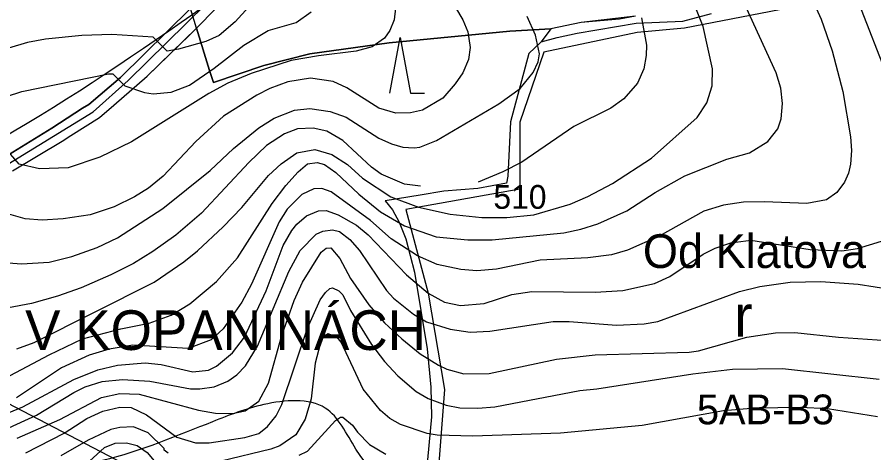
# Model space of a CAD drawing. Extents: x -684583 to -680383, y -1157874 to -1154904.
# Drawn here: x -683807 to -683375.1, y -1157544.1 to -1157324.4 of the extents above; entities that cross this region are included whole.
import ezdxf

# ---------------------------------------------------------------- set-up
doc = ezdxf.new("R2010")
doc.units = 0
for name, color, linetype in [('01_DOPRAVA', 7, 'Continuous'), ('01_MÍSTNÍ_NÁZVY', 7, 'Continuous'), ('01_VRSTEVNICE', 7, 'Continuous'), ('02_KULTURY STAV', 7, 'Continuous'), ('04_ZPF_OP_ORGAN', 7, 'Continuous'), ('06_BIOGEOGRAFIE', 7, 'Continuous'), ('06_ÚSES_BC', 7, 'Continuous')]:
    doc.layers.add(name, color=color, linetype=linetype)

msp = doc.modelspace()

# ---------------------------------------------------------------- linework, layer by layer
at = {"layer": '01_DOPRAVA'}
msp.add_lwpolyline([(-683848.9, -1157421.35), (-683768.73, -1157372.16), (-683751.13, -1157356.37), (-683692.43, -1157298.55), (-683668.13, -1157274.02), (-683656.09, -1157268.45), (-683636.34, -1157266.75), (-683560.15, -1157260.5), (-683520.41, -1157256.3), (-683504.28, -1157253.8), (-683468.06, -1157246.75), (-683377.9, -1157224.15), (-683360.31, -1157216.54), (-683346.34, -1157208.36), (-683325.33, -1157193.59), (-683264.93, -1157143.95), (-683216.9, -1157105.1), (-683205.43, -1157097.83), (-683190.89, -1157090.67), (-683176.02, -1157086.02), (-683159.33, -1157083.06), (-683139, -1157080.79)], dxfattribs=at)
at = {"layer": '01_VRSTEVNICE'}
for points in [[(-683699.38, -1157246.32), (-683697.52, -1157251.89), (-683693.81, -1157258.73), (-683684.83, -1157281.13), (-683677.27, -1157289.83), (-683677.98, -1157301.81), (-683679.83, -1157307.66), (-683697.09, -1157326.77), (-683705.22, -1157333.62), (-683711.93, -1157336.76), (-683725.62, -1157340.61), (-683731.33, -1157341.61), (-683738.46, -1157334.48), (-683759.29, -1157333.19), (-683774.41, -1157333.76), (-683792.67, -1157335.47), (-683801.8, -1157337.19), (-683821.2, -1157342.89)], [(-683613.79, -1157275.14), (-683617.07, -1157295.82), (-683615.65, -1157313.79), (-683616.93, -1157325.78), (-683619.07, -1157331.2), (-683621.78, -1157335.05), (-683628.05, -1157339.33), (-683636.04, -1157341.61), (-683655.16, -1157343.89), (-683668.85, -1157346.32), (-683689.11, -1157352.88), (-683700.8, -1157357.73), (-683710.36, -1157362.86), (-683749.3, -1157387.25), (-683765.42, -1157395.1), (-683781.25, -1157400.38), (-683795.8, -1157400.95), (-683806.08, -1157398.52), (-683813.63, -1157389.82)], [(-683408.95, -1157309.3), (-683401.68, -1157325.49), (-683396.12, -1157341.47), (-683390.7, -1157362.01), (-683386.84, -1157384.83), (-683386.42, -1157391.68), (-683386.84, -1157398.52), (-683387.84, -1157403.09), (-683389.84, -1157407.65), (-683393.69, -1157412.79), (-683398.97, -1157416.5), (-683408.95, -1157418.49), (-683430.21, -1157417.49), (-683440.91, -1157417.78), (-683450.89, -1157419.21), (-683460.88, -1157422.34), (-683483.41, -1157434.9), (-683499.39, -1157441.89), (-683507.38, -1157444.31), (-683519.36, -1157445.74), (-683543.33, -1157447.02), (-683565.29, -1157451.59), (-683575.28, -1157452.44), (-683583.26, -1157451.73), (-683595.25, -1157449.16), (-683605.23, -1157444.88), (-683618.5, -1157436.18), (-683628.91, -1157426.91), (-683648.74, -1157412.5), (-683653.45, -1157410.79), (-683657.44, -1157410.93), (-683663.43, -1157413.93), (-683670.85, -1157421.2), (-683674.98, -1157427.62), (-683688.82, -1157459), (-683693.81, -1157468.13), (-683703.09, -1157481.68), (-683709.22, -1157487.1), (-683720.77, -1157491.53), (-683748.73, -1157489.81), (-683760.71, -1157491.81), (-683770.7, -1157494.81), (-683784.68, -1157501.23), (-683807.36, -1157516.35)], [(-683589.26, -1157314.08), (-683582.27, -1157325.78), (-683579.84, -1157331.77), (-683578.56, -1157339.75), (-683579.41, -1157345.74), (-683582.41, -1157352.59), (-683586.12, -1157358.15), (-683592.39, -1157365.29), (-683602.67, -1157371.28), (-683608.66, -1157372.71), (-683616.07, -1157372.85), (-683624.63, -1157370.42), (-683640.89, -1157360.15), (-683647.74, -1157356.87), (-683659.15, -1157355.16), (-683670.56, -1157357.01), (-683679.69, -1157360.44), (-683686.25, -1157363.72), (-683702.94, -1157374.42), (-683716.92, -1157387.11), (-683733.47, -1157404.66), (-683740.74, -1157410.65), (-683747.88, -1157415.07), (-683758.15, -1157420.06), (-683770.13, -1157424.06), (-683783.82, -1157426.2), (-683794.38, -1157426.77), (-683802.94, -1157426.2), (-683824.33, -1157420.06)], [(-683567.57, -1157436.75), (-683531.34, -1157433.19), (-683522.78, -1157431.33), (-683514.23, -1157428.62), (-683499.68, -1157422.06), (-683485.41, -1157412.93), (-683470.43, -1157404.51), (-683449.18, -1157396.1), (-683437.77, -1157392.82), (-683428.64, -1157387.11), (-683423.5, -1157380.84), (-683421.79, -1157375.7), (-683421.22, -1157368), (-683422.08, -1157360.29), (-683424.36, -1157352.59), (-683441.19, -1157315.93)], [(-683807.22, -1157491.67), (-683798.51, -1157488.53), (-683737.89, -1157458.01), (-683722.91, -1157447.88), (-683716.07, -1157442.31), (-683703.09, -1157430.19), (-683693.81, -1157420.35), (-683680.26, -1157404.37), (-683673.84, -1157398.38), (-683666, -1157392.82), (-683656.87, -1157391.25), (-683648.31, -1157393.67), (-683640.46, -1157398.81), (-683632.91, -1157405.66), (-683618.64, -1157415.07), (-683604.66, -1157420.21), (-683588.69, -1157423.77), (-683572.71, -1157425.48), (-683560.16, -1157425.48), (-683546.46, -1157424.06), (-683528.2, -1157418.78), (-683519.36, -1157414.93), (-683506.81, -1157408.37), (-683487.27, -1157395.53), (-683464.16, -1157374.99), (-683459.31, -1157367.71), (-683456.6, -1157359.15), (-683456.45, -1157350.59), (-683461.16, -1157329.2), (-683465.16, -1157319.07)], [(-683368.16, -1157354.3), (-683382.57, -1157317.79)], [(-683843.45, -1157374.56), (-683804.65, -1157362.01), (-683761, -1157353.02), (-683758.86, -1157353.02), (-683752.73, -1157359.01), (-683742.74, -1157362.43), (-683738.46, -1157363.15), (-683729.33, -1157362.29), (-683720.06, -1157358.73), (-683707.65, -1157350.17), (-683692.82, -1157338.61), (-683680.41, -1157331.2), (-683666.28, -1157327.2), (-683658.72, -1157321.78)], [(-683818.34, -1157447.74), (-683804.79, -1157448.88), (-683790.95, -1157448.02), (-683779.54, -1157445.17), (-683766.7, -1157440.6), (-683756.43, -1157435.75), (-683733.61, -1157420.92), (-683709.79, -1157401.8), (-683697.95, -1157390.68), (-683685.11, -1157380.26), (-683677.41, -1157375.41), (-683667.14, -1157371.42), (-683659.44, -1157370.56), (-683649.17, -1157371.99), (-683641.18, -1157374.84), (-683624.63, -1157385.4), (-683618.36, -1157388.4), (-683612.65, -1157389.96), (-683606.94, -1157390.39), (-683604.09, -1157389.96), (-683595.53, -1157386.68), (-683564.15, -1157368.14), (-683553.45, -1157360.44), (-683546.89, -1157352.31), (-683544.32, -1157347.03), (-683543.75, -1157342.89), (-683545.61, -1157333.48), (-683549.89, -1157324.06)], [(-683492.26, -1157324.78), (-683489.69, -1157338.61), (-683489.83, -1157343.75), (-683491.12, -1157350.59), (-683494.25, -1157357.73), (-683501.24, -1157365.71), (-683507.66, -1157370.42), (-683526.35, -1157379.55), (-683552.6, -1157397.53), (-683562.15, -1157402.52), (-683574.56, -1157407.65)], [(-683603.66, -1157409.65), (-683611.79, -1157408.65), (-683623.49, -1157403.66), (-683628.34, -1157400.09), (-683642.89, -1157386.68), (-683650.88, -1157381.98), (-683657.72, -1157380.41), (-683665.71, -1157380.84), (-683672.28, -1157383.26), (-683681.26, -1157389.11), (-683690.25, -1157397.67), (-683714.07, -1157423.34), (-683727.05, -1157434.33), (-683738.6, -1157442.6), (-683748.3, -1157448.59), (-683759.86, -1157454.44), (-683774.69, -1157460.86), (-683786.68, -1157465.14), (-683799.8, -1157468.85), (-683825.76, -1157473.7)], [(-683816.06, -1157507.93), (-683790.95, -1157494.66), (-683774.12, -1157486.68), (-683754.72, -1157481.54), (-683740.46, -1157478.83), (-683729.33, -1157474.7), (-683719.92, -1157468.99), (-683706.51, -1157457.72), (-683695.95, -1157445.88), (-683678.41, -1157418.49), (-683671.56, -1157409.36), (-683665.29, -1157402.38), (-683660.72, -1157398.38), (-683655.73, -1157397.67), (-683652.02, -1157398.81), (-683646.31, -1157402.8), (-683634.76, -1157413.64), (-683623.92, -1157422.63), (-683611.79, -1157429.62), (-683595.82, -1157435.18), (-683579.84, -1157436.75), (-683567.57, -1157436.75)], [(-683818.06, -1157526.62), (-683804.08, -1157520.91), (-683778.4, -1157507.07), (-683766.42, -1157502.23), (-683756.43, -1157499.94), (-683742.46, -1157498.8), (-683734.47, -1157499.52), (-683718.49, -1157503.22), (-683710.5, -1157502.37), (-683706.51, -1157500.37), (-683698.38, -1157493.67), (-683692.39, -1157485.82), (-683681.4, -1157462.43), (-683672.85, -1157439.6), (-683668.57, -1157432.04), (-683666, -1157428.91), (-683661.15, -1157424.63), (-683655.16, -1157422.06), (-683651.16, -1157421.92), (-683645.17, -1157424.06), (-683635.9, -1157429.33), (-683630.05, -1157434.18), (-683610.79, -1157454.44), (-683599.81, -1157463.57), (-683591.54, -1157468.13), (-683583.55, -1157469.85), (-683571.57, -1157468.85), (-683557.59, -1157464.28), (-683547.6, -1157462.86), (-683515.65, -1157463.14), (-683501.67, -1157462.28), (-683485.7, -1157458.72), (-683477.99, -1157455.3), (-683461.16, -1157443.88), (-683455.17, -1157440.89), (-683447.18, -1157438.18), (-683437.2, -1157436.89), (-683407.24, -1157441.6), (-683391.27, -1157442.31), (-683383.28, -1157441.17), (-683371.3, -1157437.32)], [(-683817.2, -1157534.18), (-683797.23, -1157525.19), (-683778.4, -1157513.78), (-683772.7, -1157510.93), (-683764.14, -1157508.22), (-683753.87, -1157507.08), (-683740.17, -1157508.07), (-683719.63, -1157511.92), (-683714.92, -1157511.92), (-683707.65, -1157510.78), (-683700.8, -1157508.07), (-683696.24, -1157504.79), (-683691.96, -1157500.23), (-683685.83, -1157490.39), (-683670.13, -1157452.73), (-683664.29, -1157442.17), (-683656.3, -1157433.9), (-683652.88, -1157432.33), (-683648.03, -1157431.62), (-683644.46, -1157432.61), (-683639.32, -1157436.61), (-683634.47, -1157442.17), (-683620.78, -1157462.28), (-683617.21, -1157466.14), (-683607.23, -1157474.27), (-683600.67, -1157478.12), (-683588.69, -1157481.83), (-683578.7, -1157483.25), (-683568.72, -1157482.83), (-683536.76, -1157477.98), (-683528.78, -1157477.83), (-683504.81, -1157479.69), (-683490.83, -1157479.12), (-683483.98, -1157477.83), (-683442.9, -1157462.71), (-683432.63, -1157460.29), (-683417.23, -1157458.15), (-683401.82, -1157457.72), (-683382.99, -1157459.15), (-683365.88, -1157461.71)], [(-683807.07, -1157536.74), (-683785.53, -1157527.33), (-683764.42, -1157516.21), (-683755.29, -1157514.21), (-683745.59, -1157514.49), (-683715.64, -1157522.62), (-683707.08, -1157524.05), (-683698.52, -1157524.33), (-683692.1, -1157522.91), (-683685.26, -1157518.06), (-683680.26, -1157508.93), (-683673.7, -1157485.54), (-683667.28, -1157467.28), (-683663.15, -1157458.15), (-683653.73, -1157442.89), (-683651.16, -1157440.89), (-683648.88, -1157440.75), (-683644.32, -1157446.17), (-683639.04, -1157456.15), (-683629.77, -1157469.56), (-683621.78, -1157478.55), (-683613.08, -1157486.68), (-683603.81, -1157494.24), (-683594.68, -1157499.94), (-683590.4, -1157501.94), (-683581.84, -1157504.36), (-683569, -1157504.08), (-683535.05, -1157496.95), (-683515.65, -1157494.66), (-683468.29, -1157493.38), (-683463.44, -1157492.67), (-683439.2, -1157485.82), (-683424.65, -1157483.54), (-683414.95, -1157483.4), (-683392.98, -1157485.82), (-683344.19, -1157489.24)], [(-683802.65, -1157544.16), (-683783.4, -1157534.18), (-683771.84, -1157526.9), (-683763.85, -1157523.05), (-683755.29, -1157521.05), (-683749.59, -1157521.34), (-683741.88, -1157524.91), (-683726.48, -1157536.17), (-683717.07, -1157539.03), (-683710.22, -1157539.17), (-683692.24, -1157536.32), (-683685.25, -1157534.46), (-683680.83, -1157530.9), (-683676.41, -1157525.48), (-683673.56, -1157519.77), (-683660.58, -1157481.26), (-683654.21, -1157466.97), (-683651.59, -1157463.28), (-683649.31, -1157461.29), (-683648.03, -1157461), (-683644.89, -1157462.43), (-683642.89, -1157464.42), (-683639.04, -1157472.41), (-683628.34, -1157489.53), (-683621.78, -1157498.09), (-683615.08, -1157505.36), (-683605.8, -1157513.21), (-683599.81, -1157516.78), (-683590.68, -1157520.06), (-683583.84, -1157521.48), (-683574.71, -1157521.62), (-683566.15, -1157520.91), (-683523.35, -1157512.64), (-683514.8, -1157511.78), (-683466.3, -1157504.22), (-683446.33, -1157501.94), (-683421.22, -1157501.65), (-683372.44, -1157506.93)], [(-683373.29, -1157525.9), (-683398.4, -1157521.91), (-683412.09, -1157521.34), (-683434.92, -1157521.62), (-683450.89, -1157522.91), (-683491.97, -1157530.33), (-683533.05, -1157534.18), (-683577.27, -1157535.75), (-683595.25, -1157535.18), (-683600.38, -1157534.46), (-683613.79, -1157529.76), (-683619.21, -1157526.76), (-683623.78, -1157522.77), (-683632.62, -1157512.07), (-683643.75, -1157488.39), (-683645.74, -1157485.82), (-683650.17, -1157484.11), (-683653.45, -1157486.11), (-683656.73, -1157498.95), (-683658.87, -1157516.92), (-683661.86, -1157527.19), (-683666.57, -1157535.03), (-683674.56, -1157540.6), (-683679.12, -1157542.31), (-683704.23, -1157548.3)], [(-683664.86, -1157545.3), (-683660.72, -1157543.31), (-683646.6, -1157527.76), (-683644.03, -1157526.19), (-683642.75, -1157526.19), (-683637.9, -1157530.18), (-683635.47, -1157533.75), (-683629.34, -1157539.88), (-683621.21, -1157544.88)], [(-683730.9, -1157544.31), (-683732.9, -1157542.74), (-683732.9, -1157542.02), (-683741.03, -1157534.03), (-683748.45, -1157531.04), (-683755.29, -1157531.32), (-683759.86, -1157532.32), (-683771.27, -1157537.74), (-683784.96, -1157545.59)], [(-683770.56, -1157548.3), (-683763, -1157541.45), (-683757.58, -1157539.31), (-683751.87, -1157539.03), (-683746.45, -1157540.45), (-683741.46, -1157543.88), (-683734.61, -1157552.15)]]:
    msp.add_lwpolyline(points, dxfattribs=at)
at = {"layer": '02_KULTURY STAV'}
for points in [[(-683833.42, -1157407.25), (-683789.54, -1157380.46), (-683774.02, -1157370.4), (-683770.95, -1157368.41), (-683754.95, -1157354.91), (-683719.55, -1157320.06), (-683690.81, -1157291.07), (-683668.95, -1157267.82), (-683685.47, -1157261.51), (-683700.54, -1157254.18), (-683720.97, -1157239.25), (-683765.75, -1157219.38), (-683778.45, -1157211.98), (-683793.07, -1157199.43), (-683792.57, -1157198.29), (-683807.61, -1157147.35)], [(-683677.03, -1157289.7), (-683716.64, -1157329.96), (-683719.55, -1157320.06)], [(-683495.33, -1157324.02), (-683522.74, -1157327.18), (-683537.92, -1157330.36), (-683558.68, -1157331.56), (-683619.52, -1157337.33), (-683659.5, -1157343.01), (-683682.65, -1157348.9), (-683708.08, -1157357.41), (-683709.99, -1157351.28), (-683716.64, -1157329.96), (-683677.03, -1157289.7)], [(-683809.4, -1157402.02), (-683784.34, -1157387.05), (-683779.96, -1157384.16), (-683765.54, -1157375.09), (-683758.34, -1157368.81), (-683741.51, -1157354.13), (-683719.95, -1157333.3), (-683716.64, -1157329.96), (-683719.55, -1157320.06), (-683754.95, -1157354.91), (-683770.95, -1157368.41), (-683774.02, -1157370.4), (-683789.54, -1157380.46), (-683833.42, -1157407.25)], [(-683495.33, -1157324.02), (-683503.36, -1157325.45), (-683522.74, -1157327.18), (-683537.92, -1157330.36), (-683542.87, -1157336.97), (-683534.72, -1157334.63), (-683524.61, -1157332.49), (-683495, -1157327.5), (-683471.44, -1157326.54), (-683456.88, -1157322.53)], [(-683809.4, -1157402.02), (-683784.34, -1157387.05), (-683779.96, -1157384.16), (-683765.54, -1157375.09), (-683758.34, -1157368.81), (-683741.51, -1157354.13), (-683716.64, -1157329.96), (-683709.99, -1157351.28), (-683708.08, -1157357.41), (-683682.65, -1157348.9), (-683659.5, -1157343.01), (-683619.52, -1157337.33), (-683558.68, -1157331.56), (-683537.92, -1157330.36), (-683542.87, -1157336.97), (-683549.1, -1157342.8), (-683558.25, -1157377.17), (-683559.57, -1157404.59), (-683560.26, -1157408.22), (-683574.76, -1157410.85), (-683591.88, -1157412.26), (-683603.9, -1157414.15), (-683621.55, -1157417.01), (-683617.86, -1157421.66), (-683614.36, -1157427.85), (-683611.04, -1157436.21), (-683606.72, -1157453.02), (-683600.31, -1157491.65), (-683598.49, -1157511), (-683598.14, -1157525.93), (-683600.18, -1157547.67)], [(-683619.16, -1157362.75), (-683613.91, -1157334.75), (-683608.66, -1157362.75), (-683601.66, -1157362.75)]]:
    msp.add_lwpolyline(points, dxfattribs=at)
at = {"layer": '04_ZPF_OP_ORGAN'}
msp.add_lwpolyline([(-683422.7, -1157320.76), (-683470.63, -1157330), (-683494.36, -1157332.23), (-683541.5, -1157342.11), (-683553.61, -1157377.33), (-683553.61, -1157411.11), (-683611.1, -1157421.47), (-683599.81, -1157463.57), (-683591.51, -1157512.13), (-683595.81, -1157566.79), (-683583.39, -1157588.94), (-683562.01, -1157609.35), (-683532.75, -1157612.52), (-683516.82, -1157624.79), (-683490.7, -1157645.82), (-683457.57, -1157655.06), (-683424.61, -1157662.07), (-683371.42, -1157663.67)], dxfattribs=at)
at = {"layer": '06_BIOGEOGRAFIE'}
for points in [[(-683605.53, -1156693.94), (-683552.15, -1156773.17), (-683505.66, -1156862.74), (-683385.12, -1156876.52), (-683240.48, -1156867.91), (-682983.91, -1156935.09), (-682923.69, -1156998.38), (-682921.97, -1157094.84), (-682923.69, -1157198.19), (-682892.7, -1157272.26), (-682746.33, -1157329.1), (-682572.41, -1157337.72), (-682417.44, -1157289.49), (-682386.73, -1157266.62)], [(-683662.04, -1156787.77), (-683658.6, -1156877.34), (-683631.05, -1156927.29), (-683541.5, -1156975.52), (-683489.85, -1157028.92), (-683414.08, -1157027.2), (-683362.42, -1157025.48), (-683360.7, -1157063.37), (-683464.02, -1157132.27), (-683493.29, -1157163.28), (-683474.35, -1157189.11), (-683407.19, -1157171.89), (-683317.65, -1157115.05), (-683269.44, -1157104.71), (-683207.44, -1157173.61), (-683186.78, -1157259.74), (-683105.85, -1157416.48), (-683069.69, -1157530.17), (-683073.13, -1157580.12), (-683097.24, -1157628.35), (-683264.27, -1157657.63), (-683431.3, -1157647.3), (-683531.17, -1157605.96), (-683636.21, -1157542.23), (-683651.71, -1157521.56), (-683682.7, -1157519.83), (-683708.53, -1157528.45), (-683818.74, -1157547.39), (-683870.4, -1157518.11), (-683980.6, -1157521.56), (-684052.92, -1157490.55), (-684171.74, -1157400.98), (-684213.07, -1157375.14), (-684250.95, -1157388.92), (-684249.23, -1157437.15), (-684237.17, -1157466.44), (-684170.02, -1157518.11), (-684097.7, -1157562.9), (-684011.6, -1157605.96), (-683953.05, -1157602.51), (-683891.06, -1157626.63), (-683835.96, -1157619.74), (-683789.47, -1157599.07), (-683713.7, -1157578.4), (-683625.88, -1157592.18), (-683551.84, -1157667.97), (-683445.07, -1157736.87), (-683346.92, -1157771.32), (-683179.89, -1157767.87), (-683081.74, -1157773.04), (-683016.71, -1157810.65), (-682999.16, -1157844)], [(-684058.34, -1157481.95), (-683939.53, -1157445.78), (-683724.28, -1157326.93), (-683638.18, -1157271.81), (-683500.43, -1157218.41), (-683460.82, -1157194.29)]]:
    msp.add_spline(points, degree=3, dxfattribs=at)
at = {"layer": '06_ÚSES_BC'}
msp.add_lwpolyline([(-683819.99, -1157514.87), (-683753.02, -1157549.74), (-683746.99, -1157568.73), (-683773, -1157647.52), (-683812.59, -1157719.92)], dxfattribs=at)

# ---------------------------------------------------------------- texts
at = {"layer": '01_MÍSTNÍ_NÁZVY'}
msp.add_text('Od Klatova', height=17, dxfattribs=at).set_placement((-683491.54, -1157450.93))
at = {"layer": '01_VRSTEVNICE'}
msp.add_text('510', height=12, dxfattribs=at).set_placement((-683566.91, -1157421.09))
at = {"layer": '02_KULTURY STAV'}
msp.add_text('r', height=21, dxfattribs=at).set_placement((-683445.54, -1157485.59))
at = {"layer": '06_BIOGEOGRAFIE'}
msp.add_text('5AB-B3', height=15, dxfattribs=at).set_placement((-683464.33, -1157529.74))
at = {"layer": '06_ÚSES_BC'}
msp.add_text('LBC V KOPANINÁCH', height=20, dxfattribs=at).set_placement((-683862.47, -1157492.27))

doc.saveas('drawing.dxf')
